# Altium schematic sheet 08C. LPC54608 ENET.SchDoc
size A4; CheckedBy: 赵金生; Author: 伍伟业; CompanyName: 广州周立功单片机科技有限公司; DocumentNumber: 10; SheetNumber: 8C; SheetTotal: 19; PageSetup: Record=PageOptions|CenterHorizontal=True|CenterVertical=True|PrintScale=1.00|XCorrection=1.00|YCorrection=1.00|PrintKind=0|BorderSize=5000000|LeftOffset=0|BottomOffset=0|Orientation=2|PaperLength=1000|PaperWidth=1000|Scale=100|PaperSource=7|PrintQuality=600|MediaType=1|DitherType=10|PaperKind=A4|PrintScaleMode=1; DesignDate: 2017-3-16; CheckDate: 2017-3-16; SheetName: LPC54608 ENET&USB; SheetVersion: V1.0; SheetDescription: LPC54608 ENET&USB
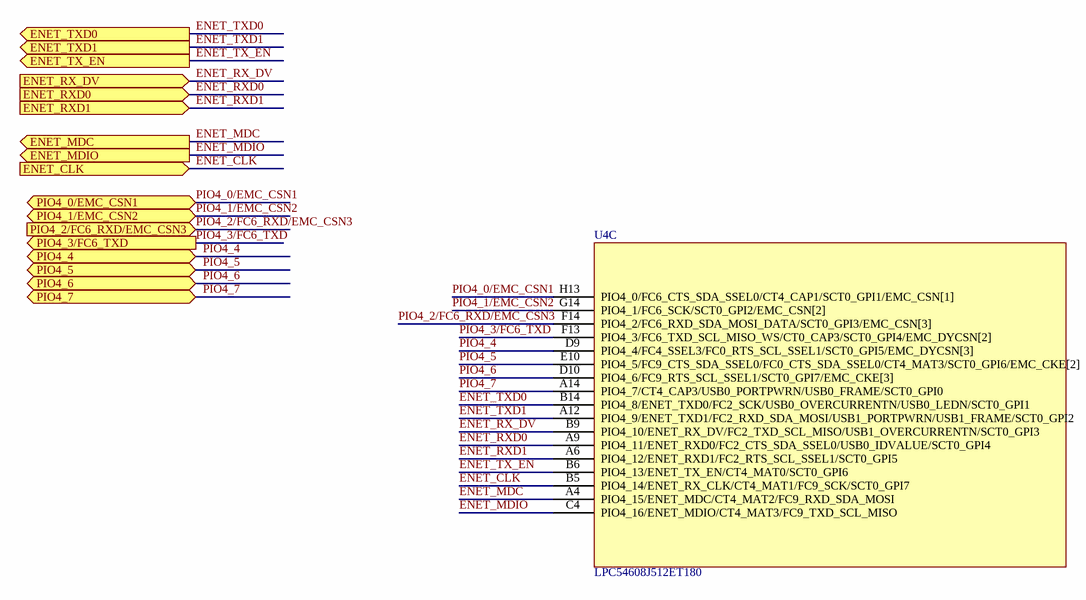
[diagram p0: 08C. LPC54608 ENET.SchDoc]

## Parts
U4  LPC54608J512ET180  [BGA180C80P14x14]  (part C of 5)

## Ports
ENET_CLK (in), ENET_MDC (out), ENET_MDIO (out), ENET_RX_DV (in), ENET_RXD0 (in), ENET_RXD1 (in), ENET_TX_EN (out), ENET_TXD0 (out), ENET_TXD1 (out), PIO4_0/EMC_CSN1 (bidir), PIO4_1/EMC_CSN2 (bidir), PIO4_2/FC6_RXD/EMC_CSN3 (in), PIO4_3/FC6_TXD (out), PIO4_4 (bidir), PIO4_5 (bidir), PIO4_6 (bidir), PIO4_7 (bidir)

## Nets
ENET_CLK: U4.B5(PIO4_14/ENET_RX_CLK/CT4_MAT1/FC9_SCK/SCT0_GPI7) ; port ENET_CLK
ENET_MDC: U4.A4(PIO4_15/ENET_MDC/CT4_MAT2/FC9_RXD_SDA_MOSI) ; port ENET_MDC
ENET_MDIO: U4.C4(PIO4_16/ENET_MDIO/CT4_MAT3/FC9_TXD_SCL_MISO) ; port ENET_MDIO
ENET_RX_DV: U4.B9(PIO4_10/ENET_RX_DV/FC2_TXD_SCL_MISO/USB1_OVERCURRENTN/SCT0_GPI3) ; port ENET_RX_DV
ENET_RXD0: U4.A9(PIO4_11/ENET_RXD0/FC2_CTS_SDA_SSEL0/USB0_IDVALUE/SCT0_GPI4) ; port ENET_RXD0
ENET_RXD1: U4.A6(PIO4_12/ENET_RXD1/FC2_RTS_SCL_SSEL1/SCT0_GPI5) ; port ENET_RXD1
ENET_TX_EN: U4.B6(PIO4_13/ENET_TX_EN/CT4_MAT0/SCT0_GPI6) ; port ENET_TX_EN
ENET_TXD0: U4.B14(PIO4_8/ENET_TXD0/FC2_SCK/USB0_OVERCURRENTN/USB0_LEDN/SCT0_GPI1) ; port ENET_TXD0
ENET_TXD1: U4.A12(PIO4_9/ENET_TXD1/FC2_RXD_SDA_MOSI/USB1_PORTPWRN/USB1_FRAME/SCT0_GPI2) ; port ENET_TXD1
PIO4_0/EMC_CSN1: U4.H13(PIO4_0/FC6_CTS_SDA_SSEL0/CT4_CAP1/SCT0_GPI1/EMC_CSN[1]) ; port PIO4_0/EMC_CSN1
PIO4_1/EMC_CSN2: U4.G14(PIO4_1/FC6_SCK/SCT0_GPI2/EMC_CSN[2]) ; port PIO4_1/EMC_CSN2
PIO4_2/FC6_RXD/EMC_CSN3: U4.F14(PIO4_2/FC6_RXD_SDA_MOSI_DATA/SCT0_GPI3/EMC_CSN[3]) ; port PIO4_2/FC6_RXD/EMC_CSN3
PIO4_3/FC6_TXD: U4.F13(PIO4_3/FC6_TXD_SCL_MISO_WS/CT0_CAP3/SCT0_GPI4/EMC_DYCSN[2]) ; port PIO4_3/FC6_TXD
PIO4_4: U4.D9(PIO4_4/FC4_SSEL3/FC0_RTS_SCL_SSEL1/SCT0_GPI5/EMC_DYCSN[3]) ; port PIO4_4
PIO4_5: U4.E10(PIO4_5/FC9_CTS_SDA_SSEL0/FC0_CTS_SDA_SSEL0/CT4_MAT3/SCT0_GPI6/EMC_CKE[2]) ; port PIO4_5
PIO4_6: U4.D10(PIO4_6/FC9_RTS_SCL_SSEL1/SCT0_GPI7/EMC_CKE[3]) ; port PIO4_6
PIO4_7: U4.A14(PIO4_7/CT4_CAP3/USB0_PORTPWRN/USB0_FRAME/SCT0_GPI0) ; port PIO4_7

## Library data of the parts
U4 = 1.05.02.0192: LPC54608J512ET180,TFBGA180,NXP,RoHS; 名称: 集成电路(临时); 贴片和直插: SMT; PCB备注: 170314lmd; 器件优选方案: 临时/偏门物料/不主推物料，谨慎选用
